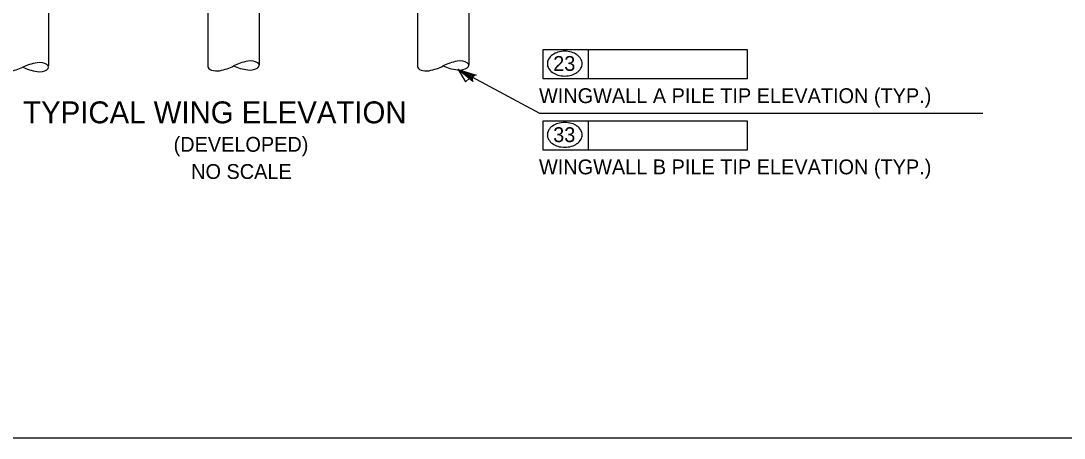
# Model space of a CAD drawing. Extents: x 635440 to 640306, y 296653 to 298484.
# Drawn here: x 638835.6 to 639046, y 297262.5 to 297346.7 of the extents above; entities that cross this region are included whole.
import ezdxf

# ---------------------------------------------------------------- set-up
doc = ezdxf.new("R2010")
doc.units = 0
for name, color, linetype in [('2', 7, 'Continuous'), ('4', 7, 'Continuous'), ('5', 7, 'Continuous')]:
    doc.layers.add(name, color=color, linetype=linetype)

msp = doc.modelspace()

# ---------------------------------------------------------------- linework, layer by layer
at = {"layer": '2'}
msp.add_line((639261.46, 297262.46), (638475.46, 297262.46), dxfattribs=at)
at = {"layer": '4'}
for p, q in [((638925.93, 297410.4), (638925.93, 297337.77)), ((638915.59, 297406.96), (638915.59, 297337.49)), ((638883.67, 297396.7), (638883.67, 297337.77)), ((638873.33, 297391.96), (638873.33, 297337.49)), ((638841.13, 297383.42), (638841.13, 297337.65))]:
    msp.add_line(p, q, dxfattribs=at)
for centre, major_axis, start_param, end_param in [((638841.14, 297334.79), (7.3, 0), 1.89032, 2.356194), ((638839.31, 297337.38), (1.83, 0), 4.455588, 8.110783), ((638883.74, 297335.18), (7.31, 0.2), 1.89032, 2.356194), ((638881.84, 297337.72), (1.83, 0.05), 4.455588, 8.110783), ((638926, 297335.18), (7.31, 0.2), 1.89032, 2.356194), ((638924.1, 297337.72), (1.83, 0.05), 4.455588, 8.110783), ((638830.81, 297339.96), (-7.3, 0), 1.89032, 2.356194), ((638841.14, 297339.96), (7.3, 0), 3.926991, 4.392865), ((638875.16, 297337.54), (-1.83, -0.05), 0, 1.827597), ((638873.26, 297340.07), (-7.31, -0.2), 1.89032, 2.356194), ((638883.6, 297340.35), (7.31, 0.2), 3.926991, 4.392865), ((638917.42, 297337.54), (-1.83, -0.05), 0, 1.827597), ((638915.52, 297340.07), (-7.31, -0.2), 1.89032, 2.356194), ((638925.86, 297340.35), (7.31, 0.2), 3.926991, 4.392865)]:
    msp.add_ellipse(centre, major_axis=major_axis, ratio=0.5, start_param=start_param, end_param=end_param, dxfattribs=at)
at = {"layer": '5'}
for p, q in [((638940.91, 297340.94), (638982.12, 297340.94)), ((638940.91, 297335.03), (638940.91, 297340.94)), ((638950.08, 297335.03), (638950.08, 297340.94)), ((638982.12, 297340.94), (638982.12, 297335.03)), ((638923.8, 297336.9), (638940.18, 297328.09)), ((638982.12, 297335.03), (638940.91, 297335.03)), ((638940.18, 297328.09), (639029.6, 297328.09)), ((638940.91, 297326.56), (638982.12, 297326.56)), ((638940.91, 297320.65), (638940.91, 297326.56)), ((638950.08, 297320.65), (638950.08, 297326.56)), ((638982.12, 297326.56), (638982.12, 297320.65)), ((638982.12, 297320.65), (638940.91, 297320.65))]:
    msp.add_line(p, q, dxfattribs=at)
msp.add_lwpolyline([(638925.29, 297334.45), (638926.01, 297335.07), (638923.79, 297336.9)], close=True, dxfattribs=at)
msp.add_lwpolyline([(638923.8, 297336.9), (638927.42, 297335.75), (638927.07, 297335.71), (638926.82, 297335.56), (638926.67, 297335.36), (638926.59, 297335.12), (638926.6, 297334.83), (638926.76, 297334.51), (638923.8, 297336.9), (638926.6, 297334.83), (638926.59, 297335.12), (638923.8, 297336.9), (638926.67, 297335.36), (638926.82, 297335.56), (638923.8, 297336.9), (638927.07, 297335.71)], dxfattribs=at)
for centre, radius, start, end in [((638944.95, 297336.89), 3.66, 106.5358, 125.6316), ((638945.29, 297335.73), 4.87, 90, 106.5358), ((638945.29, 297335.73), 4.87, 73.4642, 90), ((638945.63, 297336.89), 3.66, 54.3684, 73.4642), ((638943.61, 297338.09), 1.83, 149.9767, 180), ((638944.42, 297337.63), 2.76, 125.6316, 149.9767), ((638946.16, 297337.63), 2.76, 30.0233, 54.3684), ((638946.97, 297338.09), 1.83, 0, 30.0233), ((638943.61, 297338.09), 1.83, 180, 210.0233), ((638944.42, 297338.56), 2.76, 210.0233, 234.3684), ((638944.95, 297339.3), 3.66, 234.3684, 253.4642), ((638945.63, 297339.3), 3.66, 286.5358, 305.6316), ((638946.16, 297338.56), 2.76, 305.6316, 329.9767), ((638946.97, 297338.09), 1.83, 329.9767, 0), ((638945.29, 297340.46), 4.87, 253.4642, 270), ((638945.29, 297340.46), 4.87, 270, 286.5358), ((638944.95, 297322.51), 3.66, 106.5358, 125.6316), ((638945.29, 297321.35), 4.87, 90, 106.5358), ((638945.29, 297321.35), 4.87, 73.4642, 90), ((638945.63, 297322.51), 3.66, 54.3684, 73.4642), ((638943.61, 297323.71), 1.83, 149.9767, 180), ((638943.61, 297323.71), 1.83, 180, 210.0233), ((638944.42, 297323.25), 2.76, 125.6316, 149.9767), ((638946.16, 297323.25), 2.76, 30.0233, 54.3684), ((638946.97, 297323.71), 1.83, 0, 30.0233), ((638946.97, 297323.71), 1.83, 329.9767, 0), ((638944.42, 297324.18), 2.76, 210.0233, 234.3684), ((638944.95, 297324.91), 3.66, 234.3684, 253.4642), ((638945.29, 297326.08), 4.87, 253.4642, 270), ((638945.29, 297326.08), 4.87, 270, 286.5358), ((638945.63, 297324.91), 3.66, 286.5358, 305.6316), ((638946.16, 297324.18), 2.76, 305.6316, 329.9767)]:
    msp.add_arc(centre, radius, start, end, dxfattribs=at)

# ---------------------------------------------------------------- texts
for s, height, p in [('23', 3, (638942.96, 297336.63)), ('WINGWALL A PILE TIP ELEVATION (TYP.)', 3.0001, (638940.1, 297330.12)), ('TYPICAL WING ELEVATION', 4.4294, (638836.04, 297326.04)), ('33', 3, (638942.96, 297322.25)), ('(DEVELOPED)', 3.0001, (638866.39, 297320.3)), ('NO SCALE', 3, (638869.93, 297314.81)), ('WINGWALL B PILE TIP ELEVATION (TYP.)', 3.0001, (638940.1, 297315.74))]:
    msp.add_text(s, height=height, dxfattribs=at).set_placement(p)

doc.saveas('drawing.dxf')
